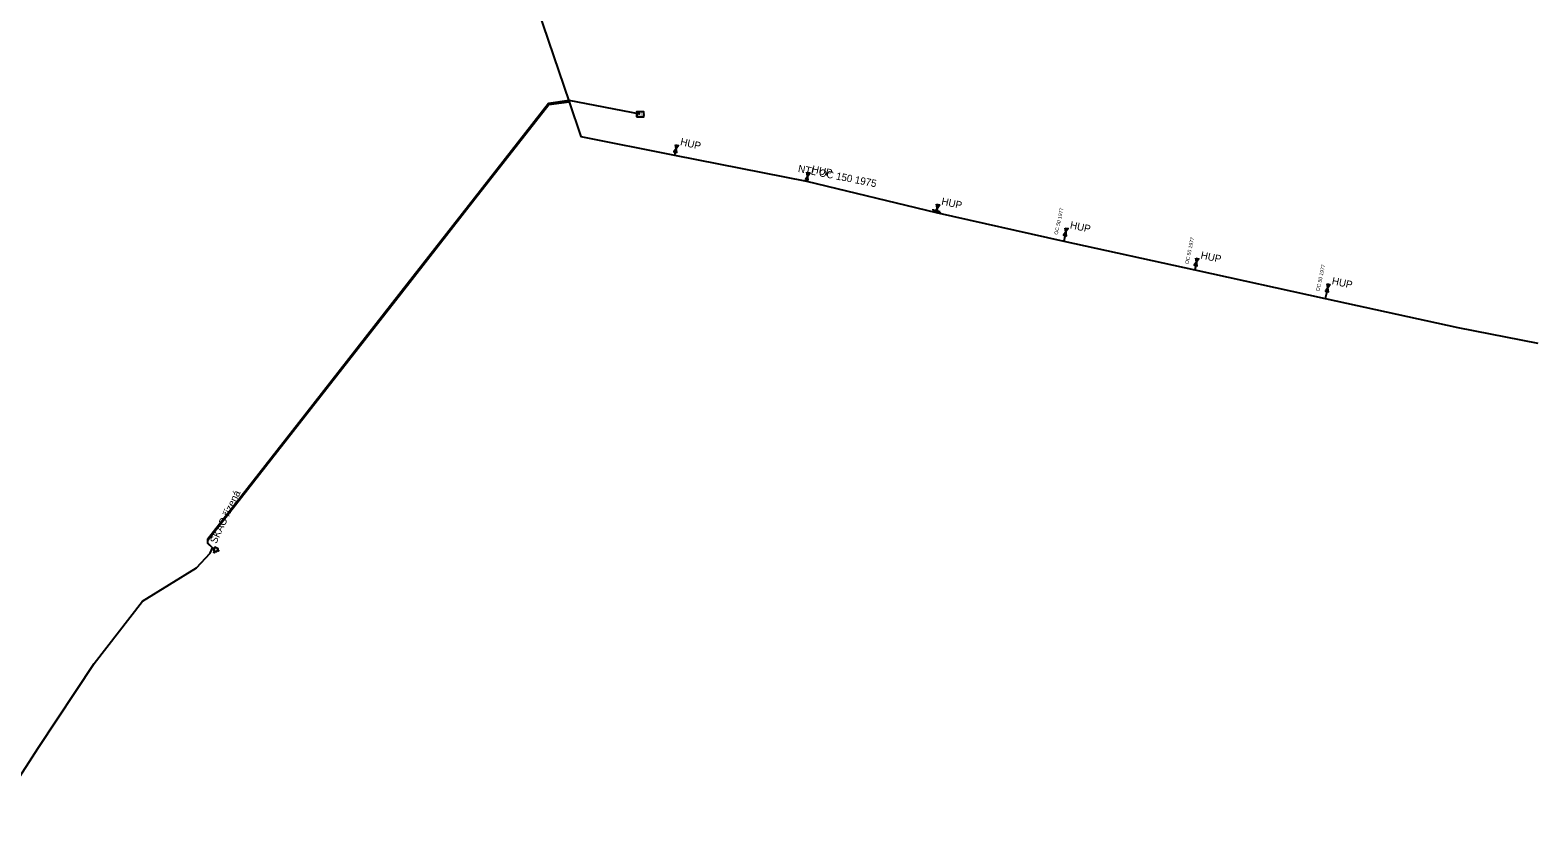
# Model space of a CAD drawing. Extents: x -743325 to -742825, y -1051501 to -1050981.
# Drawn here: x -743109.3 to -742903.9, y -1051434 to -1051324.9 of the extents above; entities that cross this region are included whole.
import ezdxf

# ---------------------------------------------------------------- set-up
doc = ezdxf.new("R2010")
doc.units = 0
for name, color, linetype in [('Kabel PKO', 7, 'Continuous'), ('NT Úsek p_ípojky - provoz', 7, 'Continuous'), ('NT Úsek plynovodu - provoz', 7, 'Continuous'), ('NT_HUP_24_popis', 7, 'Continuous'), ('Vrstva 1', 7, 'Continuous'), ('Vrstva 5', 7, 'Continuous'), ('Za_ízení PKO - provoz_popis', 7, 'Continuous')]:
    doc.layers.add(name, color=color, linetype=linetype)

msp = doc.modelspace()

# ---------------------------------------------------------------- linework, layer by layer
at = {"layer": 'Kabel PKO'}
for points in [[(-743026.22, -1051336.39), (-743035.91, -1051334.51), (-743038.72, -1051334.93), (-743048.81, -1051347.82), (-743058.8, -1051360.58), (-743071.93, -1051377.35), (-743085.18, -1051394.28), (-743085.19, -1051394.81), (-743084.5, -1051395.45)], [(-743084.5, -1051395.45), (-743085.12, -1051394.78), (-743085.12, -1051394.39), (-743071.87, -1051377.46), (-743058.74, -1051360.69), (-743048.75, -1051347.93), (-743038.66, -1051335.04), (-743035.91, -1051334.69)], [(-743115.54, -1051433.97), (-743108.22, -1051422.63), (-743100.64, -1051411.19), (-743094.02, -1051402.68), (-743086.66, -1051398.14), (-743084.84, -1051396.18), (-743084.5, -1051395.45)]]:
    msp.add_lwpolyline(points, dxfattribs=at)
at = {"layer": 'NT Úsek p_ípojky - provoz'}
for points in [[(-743021.34, -1051341.07), (-743021.54, -1051341.94)], [(-743003.43, -1051344.81), (-743003.58, -1051345.49)], [(-742985.89, -1051349.77), (-742985.85, -1051349.58)], [(-742985.85, -1051349.58), (-742985.76, -1051349.19)], [(-742968.24, -1051352.41), (-742968.52, -1051353.68)], [(-742950.44, -1051356.52), (-742950.68, -1051357.59)], [(-742932.57, -1051360.02), (-742932.89, -1051361.49)]]:
    msp.add_lwpolyline(points, dxfattribs=at)
at = {"layer": 'NT Úsek plynovodu - provoz'}
msp.add_lwpolyline([(-743057.41, -1051269.53), (-743054.24, -1051279.59), (-743051.84, -1051287.22), (-743048.77, -1051296.94), (-743035.91, -1051334.69), (-743034.31, -1051339.42), (-743021.54, -1051341.94), (-743003.58, -1051345.49), (-742985.89, -1051349.77), (-742968.52, -1051353.68), (-742950.68, -1051357.59), (-742932.89, -1051361.49), (-742914.82, -1051365.42), (-742903.94, -1051367.57)], dxfattribs=at)
at = {"layer": 'Vrstva 1'}
for p, q in [((-742986.33, -1051349.47), (-742986.3, -1051349.32)), ((-742985.36, -1051349.68), (-742986.33, -1051349.47)), ((-742985.36, -1051349.68), (-742985.39, -1051349.83))]:
    msp.add_line(p, q, dxfattribs=at)
for points in [[(-743021.42, -1051340.54), (-743021.03, -1051340.63), (-743021.65, -1051341.51), (-743021.26, -1051341.6), (-743021.42, -1051340.54)], [(-743003.52, -1051344.28), (-743003.13, -1051344.36), (-743003.73, -1051345.26), (-743003.34, -1051345.34), (-743003.52, -1051344.28)], [(-742985.85, -1051348.65), (-742985.46, -1051348.74), (-742986.06, -1051349.63), (-742985.67, -1051349.72), (-742985.85, -1051348.65)], [(-742968.33, -1051351.88), (-742967.94, -1051351.96), (-742968.54, -1051352.86), (-742968.15, -1051352.94), (-742968.33, -1051351.88)], [(-742950.53, -1051355.98), (-742950.14, -1051356.07), (-742950.75, -1051356.96), (-742950.35, -1051357.05), (-742950.53, -1051355.98)], [(-742932.65, -1051359.49), (-742932.26, -1051359.58), (-742932.87, -1051360.47), (-742932.48, -1051360.55), (-742932.65, -1051359.49)]]:
    msp.add_lwpolyline(points, dxfattribs=at)
at = {"layer": 'Vrstva 5'}
for p, q in [((-743084.5, -1051395.45), (-743084.27, -1051395.56)), ((-743084.15, -1051395.89), (-743084.27, -1051395.89)), ((-743084.26, -1051396.12), (-743084.15, -1051395.89)), ((-743084.09, -1051395.98), (-743084.15, -1051395.89)), ((-743083.6, -1051395.88), (-743083.82, -1051395.77)), ((-743083.76, -1051395.94), (-743083.66, -1051395.71)), ((-743083.71, -1051395.92), (-743083.64, -1051395.77)), ((-743083.65, -1051395.9), (-743083.62, -1051395.82))]:
    msp.add_line(p, q, dxfattribs=at)
for points in [[(-743026.72, -1051336.74), (-743025.72, -1051336.74), (-743025.72, -1051336.04), (-743026.72, -1051336.04)], [(-743083.93, -1051396), (-743083.71, -1051395.55), (-743084.17, -1051395.33), (-743084.38, -1051395.78)]]:
    msp.add_lwpolyline(points, close=True, dxfattribs=at)
msp.add_lwpolyline([(-743084.3, -1051396.1), (-743084.3, -1051396.1), (-743084.3, -1051396.09), (-743084.3, -1051396.09), (-743084.3, -1051396.09), (-743084.3, -1051396.09), (-743084.3, -1051396.09), (-743084.3, -1051396.09), (-743084.3, -1051396.08), (-743084.3, -1051396.08), (-743084.3, -1051396.08), (-743084.3, -1051396.08), (-743084.3, -1051396.08), (-743084.29, -1051396.07), (-743084.29, -1051396.07), (-743084.29, -1051396.07), (-743084.29, -1051396.07), (-743084.29, -1051396.07), (-743084.29, -1051396.07), (-743084.29, -1051396.07), (-743084.29, -1051396.06), (-743084.29, -1051396.06), (-743084.29, -1051396.06), (-743084.29, -1051396.06), (-743084.28, -1051396.06), (-743084.28, -1051396.06), (-743084.28, -1051396.06), (-743084.28, -1051396.06), (-743084.28, -1051396.05), (-743084.27, -1051396.05), (-743084.27, -1051396.05), (-743084.27, -1051396.05), (-743084.27, -1051396.05), (-743084.27, -1051396.05), (-743084.27, -1051396.05), (-743084.26, -1051396.05), (-743084.26, -1051396.05), (-743084.26, -1051396.04), (-743084.26, -1051396.04), (-743084.26, -1051396.04), (-743084.26, -1051396.04), (-743084.26, -1051396.04), (-743084.25, -1051396.03), (-743084.25, -1051396.03), (-743084.25, -1051396.03), (-743084.25, -1051396.03), (-743084.25, -1051396.03), (-743084.25, -1051396.03), (-743084.25, -1051396.02), (-743084.25, -1051396.02), (-743084.25, -1051396.02), (-743084.25, -1051396.01), (-743084.25, -1051396.01), (-743084.25, -1051396.01), (-743084.25, -1051396.01)], dxfattribs=at)

# ---------------------------------------------------------------- texts
at = {"layer": 'NT Úsek p_ípojky - provoz'}
for rotation, p in [(77.6098, (-742969.35, -1051352.83)), (77.6689, (-742951.54, -1051356.84)), (77.6038, (-742933.7, -1051360.54))]:
    msp.add_text('OC 50 1977', height=0.5, rotation=rotation, dxfattribs=at).set_placement(p)
at = {"layer": 'NT Úsek plynovodu - provoz'}
msp.add_text('NTL OC 150 1975', height=1, rotation=348.8226, dxfattribs=at).set_placement((-743004.79, -1051344.24))
at = {"layer": 'NT_HUP_24_popis'}
for rotation, p in [(346.77, (-743020.84, -1051340.57)), (347.63, (-743002.93, -1051344.31)), (347.68, (-742985.26, -1051348.69)), (347.61, (-742967.74, -1051351.91)), (347.67, (-742949.94, -1051356.02)), (347.6, (-742932.07, -1051359.52))]:
    msp.add_text('HUP', height=1, rotation=rotation, dxfattribs=at).set_placement(p)
at = {"layer": 'Vrstva 5'}
msp.add_text('RIS', height=0.472, dxfattribs=at).set_placement((-743026.62, -1051336.63))
at = {"layer": 'Za_ízení PKO - provoz_popis'}
msp.add_text('SKAO řízená', height=1, rotation=64.59, dxfattribs=at).set_placement((-743084, -1051394.95))

doc.saveas('drawing.dxf')
